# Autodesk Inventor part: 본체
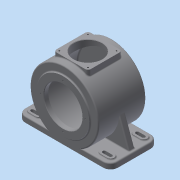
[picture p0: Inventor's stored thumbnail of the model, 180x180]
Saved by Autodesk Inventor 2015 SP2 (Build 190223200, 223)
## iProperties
Created: 2015-06
Part Number: 본체
Material: 일반
Document SubType Name: Modeling
Designer: AMC
Density: 1 g/cm^3
Appearance: 기본값
Author: AMC
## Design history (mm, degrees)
sketch "스케치1"
  geometry: L1 (-115, 59)-(115, 59); L2 (115, 59)-(115, -59); L3 (115, -59)-(-115, -59); L4 (-115, -59)-(-115, 59); 3 further points
  constraints: 8 end point, 2 midpoint, 2 parallel, 1 horizontal, 1 horizontal alignment, 1 perpendicular, 1 vertical alignment
  dimensions: "d0" = 230 distance of L2.end L3.end; "d1" = 118 distance of L1.end L2.end
extrude "돌출1" new body sketch "스케치1" distance "d2" = 14; taper "d3" = 0 deg
sketch "스케치2"
  geometry: L1 (81, 41)-(97, 41); L2 (81, 50)-(97, 50); L3 (97, 32)-(81, 32); L4 (115, 59)-(-115, 59) reference; A1 r 9 centre (81, 41) between (81, 50) and (81, 32); A2 r 9 centre (97, 41) between (97, 32) and (97, 50); 2 further points
  constraints: 8 end point, 4 point on circle, 4 tangent, 2 centre point, 1 horizontal, 1 midpoint, 1 parallel
  dimensions: "d4" = 16 distance of L1.end L1.start; "d5" = 18 distance between parallel lines of L3 L2; "d6" = 97 horizontal distance of point (0, 0) L1.end; "d7" = 18 distance from line of L4 point (89, 41)
extrude "돌출2" join sketch "스케치2" distance "d8" = 3; taper "d9" = 0 deg
sketch "스케치3"
  geometry: L1 (97, 32)-(81, 32) reference; L2 (81, 50)-(97, 50) reference; L3 (81, 41)-(97, 41); L4 (81, 45)-(97, 45); L5 (97, 37)-(81, 37); A1 r 9 centre (97, 41) between (97, 32) and (97, 50) reference; A2 r 9 centre (81, 41) between (81, 50) and (81, 32) reference; A3 r 9 centre (81, 41) between (81, 50) and (81, 32) reference; A4 r 4 centre (81, 41) between (81, 45) and (81, 37); A5 r 4 centre (97, 41) between (97, 37) and (97, 45); 2 further points
  constraints: 8 end point, 4 point on circle, 4 tangent, 2 centre point, 1 horizontal, 1 midpoint, 1 parallel
  dimensions: "d10" = 8 distance between parallel lines of L5 L4
extrude "돌출3" cut sketch "스케치3" stored distance "d11" = 3; taper "d12" = 0 deg
sketch "스케치4"
  geometry: L1 (115, 14)-(115, 0) reference; L2 (115, 0)-(-115, 0) reference; L3 (-115, 0)-(-115, 14) reference; L4 (-115, 14)-(115, 14) reference; L5 (-115, 0)-(115, 0) reference; C1 r 85 at (0, 85); 3 further points
  constraints: 2 midpoint, 1 centre point, 1 vertical alignment
  dimensions: "d15" = 170 diameter of C1; "d16" = 85 distance from line of C1.centre L2
extrude "돌출4" join sketch "스케치4" stored distance "d17" = 118; taper "d18" = 0 deg
sketch "스케치5"
  geometry: L1 (115, 0)-(-115, 0) reference; L2 (-115, 0)-(-115, 14) reference; L3 (-115, 14)-(-46.733, 14) reference; L4 (46.733, 14)-(115, 14) reference; L5 (115, 14)-(115, 0) reference; L6 (46.733, 14)-(115, 14) reference; L7 (109, 14)-(84.87, 80.297); A1 r 85 centre (0, 85) between (46.733, 14) and (-46.733, 14) reference; 1 further point
  constraints: 2 end point, 1 point on circle, 1 point on line
  dimensions: "d19" = 6 distance from line of L7.start L5; "d20" = 110 deg angle of L4 L7
feature "리브1" sketch "스케치5" dims "d21" = 1, "d22" = 15, "d23" = 0, "d24" = 0, "d25" = 1, "d26" = 1
sketch "스케치6"
  geometry: L1 (161.733, 14)-(230, 14) reference; L2 (230, 14)-(230, 0) reference; L3 (230, 0)-(0, 0) reference; L4 (0, 0)-(0, 14) reference; L5 (0, 14)-(68.267, 14) reference; C1 r 65 at (115, 85); A1 r 85 centre (115, 85) between (161.733, 14) and (68.267, 14) reference; 1 further point
  constraints: 1 centre point, 1 coincident
  dimensions: "d27" = 130 diameter of C1
extrude "돌출5" join sketch "스케치6" distance "d28" = 3; taper "d29" = 0 deg
sketch "스케치7"
  geometry: C1 r 47.5 at (0, 0); C2 r 65 at (0, 0) reference; 1 further point
  constraints: 1 centre point, 1 coincident
  dimensions: "d30" = 95 diameter of C1
extrude "돌출6" cut sketch "스케치7" distance "d31" = 11; taper "d32" = 0 deg
node "작업 평면2"
  node "작업 평면1"
sketch "스케치8"
  geometry: L1 (-42.5, 42.5)-(42.5, 42.5); L2 (42.5, 42.5)-(42.5, -42.5); L3 (42.5, -42.5)-(-42.5, -42.5); L4 (-42.5, -42.5)-(-42.5, 42.5); 3 further points
  constraints: 8 end point, 2 midpoint, 2 parallel, 1 horizontal, 1 horizontal alignment, 1 perpendicular, 1 vertical alignment
  dimensions: "d34" = 85 distance of L1.start L1.end; "d35" = 85 distance of L1.end L2.end
extrude "돌출7" join sketch "스케치8" stored distance "d36" = 11; taper "d37" = 0 deg
sketch "스케치9"
  geometry: L1 (-51, 162)-(51, 162); L2 (51, 162)-(51, 8); L3 (51, 8)-(-51, 8); L4 (-51, 8)-(-51, 162); L5 (-59, 0)-(59, 0) reference; L6 (-59, 170)-(-59, 14) reference; L7 (59, 14)-(59, 170) reference; L8 (51, 85)-(-51, 85); 1 further point
  constraints: 10 end point, 2 midpoint, 2 parallel, 1 horizontal, 1 perpendicular
  dimensions: "d38" = 8 distance between parallel lines of L5 L3; "d39" = 8 distance between parallel lines of L6 L4; "d40" = 8 distance between parallel lines of L7 L2; "d41" = 154 distance of L1.end L2.end
revolve "회전1" sketch "스케치9" stored, may be unused: angle "d42" = 90 deg
sketch "스케치10"
  geometry: C1 r 35 at (0, 0); 1 further point
  constraints: 1 centre point, 1 coincident
  dimensions: "d43" = 70 diameter of C1
extrude "돌출8" cut sketch "스케치10" distance "d44" = 48; taper "d45" = 0 deg
sketch "스케치11"
  geometry: 2 further points
  dimensions: "d46" = 35.5 horizontal distance of point (0, 0) point (35.5, 35.5); "d47" = 35.5 horizontal distance of point (0, 0) point (35.5, 35.5)
hole "구멍1" sketch "스케치11" at (35.5, 35.5) diameter "d48" = 3.242; stored, may be unused: countersink angle "d52" = 90 deg, drill point angle "d54" = 118 deg; dims "d49" = 10, "d50" = 4, "d51" = 2, "d53" = 13
fillet "모깎기1" dims "d58" = 7
fillet "모깎기2" dims "d59" = 18
fillet "모깎기3" dims "d60" = 3
sketch "스케치12"
  geometry: L1 (55.179, -11)-(0, -11) reference; L2 (0, 0)-(0, -11) reference; L3 (0, 0)-(194, 0) reference; L4 (194, 0)-(194, -11) reference; L5 (194, -11)-(138.821, -11) reference; C1 r 65 at (97, -85); A1 r 85 centre (97, -85) between (55.179, -11) and (138.821, -11) reference; 1 further point
  constraints: 1 centre point, 1 coincident
  dimensions: "d61" = 130 diameter of C1
extrude "돌출9" join sketch "스케치12" distance "d62" = 13; taper "d63" = 0 deg
sketch "스케치21"
  geometry: L1 (-108.18, -71)-(-46.733, -71) reference; L2 (46.733, -71)-(108.18, -71) reference; L3 (111.967, -74)-(111.967, -85) reference; L4 (111.967, -85)-(-111.967, -85) reference; L5 (-111.967, -85)-(-111.967, -74) reference; C1 r 77 at (0, 0) reference; C2 r 31 at (0, 0); A1 r 85 centre (0, 0) between (46.733, -71) and (-46.733, -71) reference; 1 further point
  constraints: 1 centre point, 1 coincident, 2 other
  dimensions: "d73" = 62 diameter of C2
extrude "돌출13" join sketch "스케치21" distance "d74" = 3.5; taper "d75" = -25 deg
sketch "스케치23"
  geometry: L1 (46.733, -71)-(74.775, -71) reference; L2 (74.775, -71)-(74.775, -68) reference; L3 (74.775, -68)-(103.225, -68) reference; L4 (103.225, -68)-(103.225, -71) reference; L5 (103.225, -71)-(110.519, -71) reference; L6 (113.785, -74)-(113.785, -85) reference; L7 (113.785, -85)-(-113.785, -85) reference; L8 (-113.785, -85)-(-113.785, -74) reference; L9 (-110.519, -71)-(-103.225, -71) reference; L10 (-103.225, -71)-(-103.225, -68) reference; L11 (-103.225, -68)-(-74.775, -68) reference; L12 (-74.775, -68)-(-74.775, -71) reference; L13 (-74.775, -71)-(-46.733, -71) reference; C1 r 29.368 at (0, 0) reference; C2 r 77 at (0, 0) reference; C3 r 23.5 at (0, 0); A1 r 85 centre (0, 0) between (46.733, -71) and (-46.733, -71) reference; 1 further point
  constraints: 1 centre point, 1 coincident, 2 other
  dimensions: "d76" = 47 diameter of C3
extrude "돌출14" cut sketch "스케치23" distance "d77" = 14; taper "d78" = 0 deg
sketch "스케치24"
  geometry: C1 r 23.5 at (0, 0) reference; C2 r 65 at (0, 0) reference; C3 r 15 at (0, 0); 1 further point
  constraints: 1 centre point, 1 coincident
  dimensions: "d79" = 30 diameter of C3
extrude "돌출15" cut sketch "스케치24" distance "d80" = 3; taper "d81" = 0 deg
sketch "스케치26"
  geometry: C1 r 47.5 at (0, 0) reference; C2 r 65 at (0, 0) reference; 2 further points
  constraints: 1 vertical alignment
  dimensions: "d82" = 55 distance of C1.centre point (0, 55)
hole "구멍2" sketch "스케치26" at (0, 55) diameter "d83" = 3.242; stored, may be unused: countersink angle "d87" = 90 deg, drill point angle "d89" = 118 deg; dims "d84" = 8, "d85" = 4, "d86" = 2, "d88" = 11.8
sketch "스케치27"
  geometry: 1 further point
chamfer "모따기1" distance "d93" = 1; stored, may be unused: second distance "d94" = 2, angle "d95" = 45 deg
fillet "모깎기4" dims "d96" = 3
fillet "모깎기5" dims "d97" = 3
fillet "모깎기6" dims "d98" = 3
fillet "모깎기7" dims "d99" = 3
fillet "모깎기8" dims "d100" = 3
fillet "모깎기9" dims "d101" = 3
fillet "모깎기10" dims "d102" = 3
chamfer "모따기2" distance "d103" = 1; stored, may be unused: second distance "d104" = 2, angle "d105" = 45 deg
fillet "모깎기11" dims "d106" = 3
fillet "모깎기12" dims "d107" = 3
fillet "모깎기13" dims "d108" = 3
fillet "모깎기14" dims "d109" = 3
node "솔리드1"
mirror "대칭1"
mirror "대칭2"
mirror "대칭3"
pattern_circular "원형 패턴1" dims angle "d56" = 360 deg
pattern_circular "원형 패턴2" dims angle "d91" = 360 deg
node "절단 모서리 투영1"
node "절단 모서리 투영2"
node "절단 모서리 투영3"
node "절단 모서리 투영4"
node "절단 모서리 투영5"
node "절단 모서리 투영6"
node "절단 모서리 투영11"
node "절단 모서리 투영13"
node "절단 모서리 투영14"
node "절단 모서리 투영15"
other parameters: "d33" = 3
